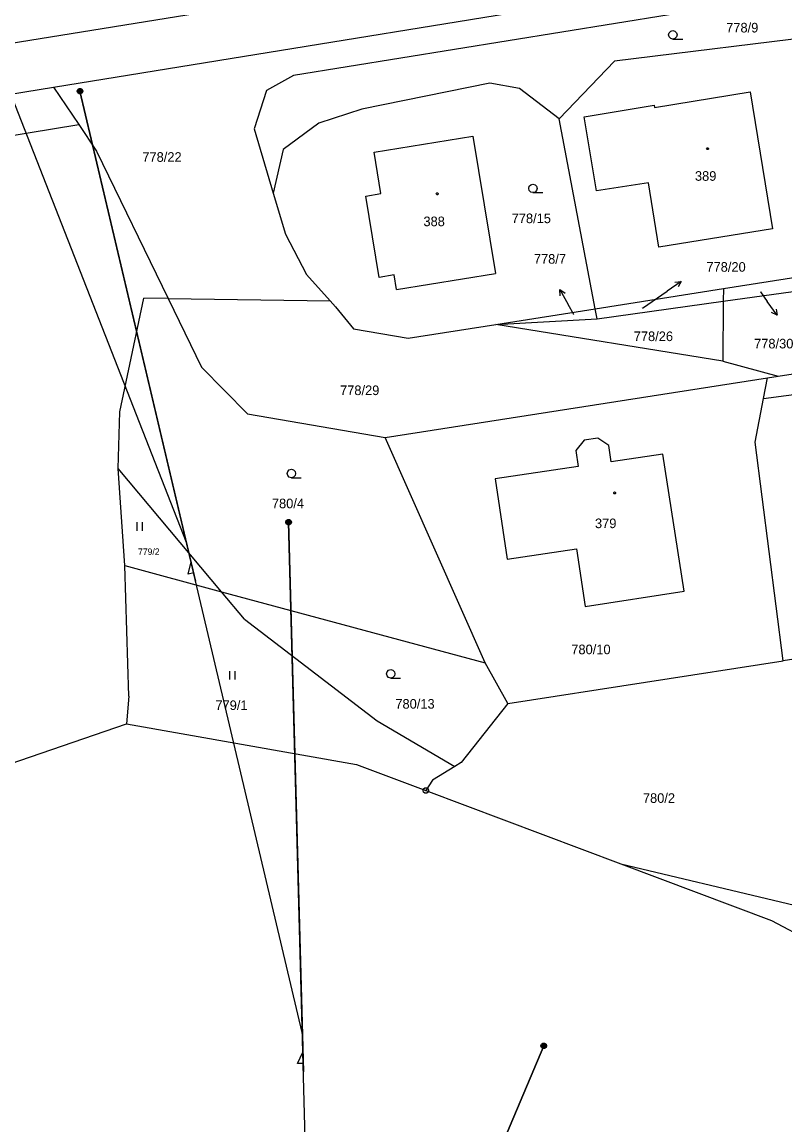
# Model space of a CAD drawing. Extents: x -747792 to -745414, y -1093712 to -1091463.
# Drawn here: x -746030.8 to -745963.3, y -1091690.6 to -1091593 of the extents above; entities that cross this region are included whole.
import ezdxf

# ---------------------------------------------------------------- set-up
doc = ezdxf.new("R2010")
doc.units = 0
for name, color, linetype in [('Budovy', 7, 'Continuous'), ('Doplňkové značky', 7, 'Continuous'), ('Doplňující texty', 7, 'Continuous'), ('Koleje_dopravní prvky', 7, 'Continuous'), ('Kultury', 7, 'Continuous'), ('Ploty_opěrné zdi', 7, 'Continuous'), ('Stromy_porost', 7, 'Continuous'), ('Značky IS', 7, 'Continuous')]:
    doc.layers.add(name, color=color, linetype=linetype)

msp = doc.modelspace()

# ---------------------------------------------------------------- linework, layer by layer
at = {"layer": 'Budovy'}
for points in [[(-745973.24, -1091594.46), (-745973.43, -1091594.41), (-745973.565, -1091594.27), (-745973.615, -1091594.085), (-745973.565, -1091593.9), (-745973.43, -1091593.76), (-745973.24, -1091593.71), (-745973.05, -1091593.76), (-745972.915, -1091593.9), (-745972.865, -1091594.085), (-745972.915, -1091594.27), (-745973.05, -1091594.41), (-745973.24, -1091594.46), (-745972.365, -1091594.46)], [(-745985.62, -1091608.06), (-745985.81, -1091608.01), (-745985.945, -1091607.87), (-745985.995, -1091607.685), (-745985.945, -1091607.5), (-745985.81, -1091607.36), (-745985.62, -1091607.31), (-745985.43, -1091607.36), (-745985.295, -1091607.5), (-745985.245, -1091607.685), (-745985.295, -1091607.87), (-745985.43, -1091608.01), (-745985.62, -1091608.06), (-745984.745, -1091608.06)], [(-746007, -1091633.3), (-746007.19, -1091633.25), (-746007.325, -1091633.11), (-746007.375, -1091632.925), (-746007.325, -1091632.74), (-746007.19, -1091632.6), (-746007, -1091632.55), (-746006.81, -1091632.6), (-746006.675, -1091632.74), (-746006.625, -1091632.925), (-746006.675, -1091633.11), (-746006.81, -1091633.25), (-746007, -1091633.3), (-746006.125, -1091633.3)], [(-746020.67, -1091637.24), (-746020.67, -1091637.99)], [(-746020.17, -1091637.99), (-746020.17, -1091637.24)], [(-746012.47, -1091650.41), (-746012.47, -1091651.16)], [(-746011.97, -1091651.16), (-746011.97, -1091650.41)], [(-745998.21, -1091651.03), (-745998.4, -1091650.98), (-745998.535, -1091650.84), (-745998.585, -1091650.655), (-745998.535, -1091650.47), (-745998.4, -1091650.33), (-745998.21, -1091650.28), (-745998.02, -1091650.33), (-745997.885, -1091650.47), (-745997.835, -1091650.655), (-745997.885, -1091650.84), (-745998.02, -1091650.98), (-745998.21, -1091651.03), (-745997.335, -1091651.03)]]:
    msp.add_lwpolyline(points, dxfattribs=at)
at = {"layer": 'Doplňkové značky'}
for points in [[(-745983.244, -1091616.648), (-745982.5, -1091617.95)], [(-745983.213, -1091617.206), (-745983.244, -1091616.648), (-745982.779, -1091616.958)], [(-745972.507, -1091615.916), (-745973.74, -1091616.77)], [(-745973.06, -1091615.995), (-745972.507, -1091615.916), (-745972.776, -1091616.406)], [(-745975.92, -1091618.28), (-745973.74, -1091616.77)], [(-745965.49, -1091616.85), (-745964.88, -1091617.7)], [(-745964.006, -1091618.919), (-745964.88, -1091617.7)], [(-745981.99, -1091618.85), (-745982.5, -1091617.95)], [(-745964.094, -1091618.367), (-745964.006, -1091618.919), (-745964.5, -1091618.658)]]:
    msp.add_lwpolyline(points, dxfattribs=at)
at = {"layer": 'Doplňující texty'}
msp.add_lwpolyline([(-745995.025, -1091660.75), (-745994.9, -1091660.845), (-745994.85, -1091660.99), (-745994.9, -1091661.135), (-745995.025, -1091661.23), (-745995.175, -1091661.23), (-745995.3, -1091661.135), (-745995.35, -1091660.99), (-745995.3, -1091660.845), (-745995.175, -1091660.75)], close=True, dxfattribs=at)
msp.add_lwpolyline([(-745995.125, -1091660.99), (-745995.075, -1091660.99)], dxfattribs=at)
at = {"layer": 'Kultury'}
msp.add_lwpolyline([(-746047.89, -1091597.41), (-745968.74, -1091584.63)], dxfattribs=at)
at = {"layer": 'Ploty_opěrné zdi'}
for points in [[(-745970.17, -1091604.085), (-745970.12, -1091604.095), (-745970.095, -1091604.14), (-745970.085, -1091604.17), (-745970.095, -1091604.215), (-745970.135, -1091604.25), (-745970.17, -1091604.255), (-745970.215, -1091604.24), (-745970.245, -1091604.21), (-745970.255, -1091604.17), (-745970.245, -1091604.125), (-745970.205, -1091604.09)], [(-745994.09, -1091608.075), (-745994.04, -1091608.085), (-745994.015, -1091608.13), (-745994.005, -1091608.16), (-745994.015, -1091608.205), (-745994.055, -1091608.24), (-745994.09, -1091608.245), (-745994.135, -1091608.23), (-745994.165, -1091608.2), (-745994.175, -1091608.16), (-745994.165, -1091608.115), (-745994.125, -1091608.08)], [(-745978.39, -1091634.555), (-745978.34, -1091634.565), (-745978.315, -1091634.61), (-745978.305, -1091634.64), (-745978.315, -1091634.685), (-745978.355, -1091634.72), (-745978.39, -1091634.725), (-745978.435, -1091634.71), (-745978.465, -1091634.68), (-745978.475, -1091634.64), (-745978.465, -1091634.595), (-745978.425, -1091634.56)]]:
    msp.add_lwpolyline(points, close=True, dxfattribs=at)
at = {"layer": 'Stromy_porost'}
for points in [[(-746028.05, -1091598.72), (-745968.8, -1091589.06)], [(-745968.83, -1091591.55), (-746006.8, -1091597.68)], [(-745959.19, -1091594.06), (-745978.41, -1091596.41)], [(-745978.41, -1091596.41), (-745983.31, -1091601.54)], [(-746006.8, -1091597.68), (-746009.21, -1091599.02)], [(-746046.56, -1091601.74), (-746028.05, -1091598.72)], [(-746028.05, -1091598.72), (-746025.82, -1091602.04)], [(-746009.21, -1091599.02), (-746010.28, -1091602.42)], [(-745989.44, -1091598.37), (-746000.77, -1091600.68)], [(-745986.8, -1091598.84), (-745989.44, -1091598.37)], [(-745983.31, -1091601.54), (-745986.8, -1091598.84)], [(-745974.86, -1091600.51), (-745966.39, -1091599.13)], [(-745966.39, -1091599.13), (-745964.41, -1091611.26)], [(-746000.77, -1091600.68), (-746004.58, -1091601.91)], [(-745981.09, -1091601.36), (-745974.88, -1091600.33)], [(-745974.88, -1091600.33), (-745974.86, -1091600.51)], [(-746041.61, -1091604.62), (-746025.82, -1091602.04)], [(-746025.82, -1091602.04), (-746024.25, -1091604.39)], [(-746004.58, -1091601.91), (-746007.72, -1091604.24)], [(-745980.12, -1091618.34), (-745983.31, -1091601.54)], [(-745980.01, -1091607.91), (-745981.09, -1091601.36)], [(-746010.28, -1091602.42), (-746008.61, -1091608.11)], [(-745999.67, -1091604.47), (-745990.93, -1091603.06)], [(-745990.93, -1091603.06), (-745988.93, -1091615.23)], [(-746024.25, -1091604.39), (-746017.9, -1091617.43)], [(-746007.72, -1091604.24), (-746008.61, -1091608.11)], [(-745999.08, -1091608.14), (-745999.67, -1091604.47)], [(-745975.4, -1091607.19), (-745980.01, -1091607.91)], [(-745974.48, -1091612.9), (-745975.4, -1091607.19)], [(-746008.61, -1091608.11), (-746007.53, -1091611.75)], [(-746000.41, -1091608.36), (-745999.08, -1091608.14)], [(-745999.24, -1091615.56), (-746000.41, -1091608.36)], [(-746007.53, -1091611.75), (-746005.66, -1091615.32)], [(-745964.41, -1091611.26), (-745974.48, -1091612.9)], [(-745968.77, -1091616.55), (-745955.77, -1091614.51)], [(-746005.66, -1091615.32), (-746003.57, -1091617.65)], [(-745997.91, -1091615.35), (-745999.24, -1091615.56)], [(-745997.7, -1091616.63), (-745997.91, -1091615.35)], [(-745997.7, -1091616.63), (-745988.93, -1091615.23)], [(-745980.12, -1091618.34), (-745968.77, -1091616.55)], [(-745968.78, -1091617.68), (-745955.54, -1091615.85)], [(-745968.77, -1091616.55), (-745968.78, -1091617.68)], [(-746022.18, -1091627.45), (-746020.05, -1091617.4)], [(-746017.9, -1091617.43), (-746020.05, -1091617.4)], [(-746017.9, -1091617.43), (-746003.57, -1091617.65)], [(-746017.9, -1091617.43), (-746014.94, -1091623.51)], [(-746003.57, -1091617.65), (-746003.09, -1091618.18)], [(-745979.95, -1091619.23), (-745968.78, -1091617.68)], [(-745968.78, -1091617.68), (-745968.83, -1091622.99)], [(-746003.09, -1091618.18), (-746001.49, -1091620.11)], [(-745988.92, -1091619.73), (-745980.12, -1091618.34)], [(-745979.95, -1091619.23), (-745980.12, -1091618.34)], [(-745988.92, -1091619.73), (-745979.95, -1091619.23)], [(-746001.49, -1091620.11), (-745996.67, -1091620.95)], [(-745996.67, -1091620.95), (-745988.92, -1091619.73)], [(-745968.83, -1091622.99), (-745988.92, -1091619.73)], [(-745963.91, -1091624.31), (-745946.44, -1091621.58)], [(-746014.94, -1091623.51), (-746010.87, -1091627.63)], [(-745968.83, -1091622.99), (-745963.91, -1091624.31)], [(-745965.23, -1091626.27), (-745941.81, -1091623.17)], [(-745998.7, -1091629.75), (-745964.87, -1091624.46)], [(-745965.23, -1091626.27), (-745964.87, -1091624.46)], [(-745964.87, -1091624.46), (-745963.91, -1091624.31)], [(-745965.97, -1091630.16), (-745965.23, -1091626.27)], [(-746022.34, -1091632.47), (-746022.18, -1091627.45)], [(-746010.87, -1091627.63), (-745998.7, -1091629.75)], [(-745989.84, -1091649.69), (-745998.7, -1091629.75)], [(-745981.09, -1091629.96), (-745981.83, -1091630.88)], [(-745979.89, -1091629.78), (-745981.09, -1091629.96)], [(-745978.92, -1091630.43), (-745979.89, -1091629.78)], [(-745978.71, -1091631.88), (-745978.92, -1091630.43)], [(-745963.48, -1091649.5), (-745965.97, -1091630.16)], [(-745981.83, -1091630.88), (-745981.63, -1091632.31)], [(-745974.14, -1091631.2), (-745978.71, -1091631.88)], [(-745972.25, -1091643.33), (-745974.14, -1091631.2)], [(-745981.63, -1091632.31), (-745988.95, -1091633.4)], [(-746021.73, -1091641.08), (-746022.34, -1091632.47)], [(-746013.19, -1091643.39), (-746022.34, -1091632.47)], [(-745988.95, -1091633.4), (-745987.89, -1091640.51)], [(-745987.89, -1091640.51), (-745981.76, -1091639.58)], [(-745981.76, -1091639.58), (-745980.99, -1091644.7)], [(-746021.37, -1091652.64), (-746021.73, -1091641.08)], [(-746021.73, -1091641.08), (-746013.19, -1091643.39)], [(-746013.19, -1091643.39), (-745989.84, -1091649.69)], [(-746011.15, -1091645.82), (-746013.19, -1091643.39)], [(-745980.99, -1091644.7), (-745972.25, -1091643.33)], [(-746011.15, -1091645.82), (-745999.4, -1091654.83)], [(-745945.61, -1091646.72), (-745963.48, -1091649.5)], [(-745987.84, -1091653.29), (-745989.84, -1091649.69)], [(-745987.84, -1091653.29), (-745963.48, -1091649.5)], [(-746021.37, -1091652.64), (-746021.58, -1091655.08)], [(-745987.84, -1091653.29), (-745991.96, -1091658.52), (-745992.53, -1091658.86)], [(-745999.4, -1091654.83), (-745992.53, -1091658.86)], [(-746172.9, -1091707.09), (-746021.58, -1091655.08)], [(-746021.58, -1091655.08), (-746001.24, -1091658.68)], [(-746001.24, -1091658.68), (-745995.1, -1091660.99)], [(-745992.53, -1091658.86), (-745994.51, -1091660.06), (-745995.1, -1091660.99)], [(-745995.1, -1091660.99), (-745977.84, -1091667.47)], [(-745977.84, -1091667.47), (-745964.51, -1091672.48)], [(-745977.84, -1091667.47), (-745949.59, -1091674.19)], [(-745964.51, -1091672.48), (-745950.71, -1091679.81)]]:
    msp.add_lwpolyline(points, dxfattribs=at)
at = {"layer": 'Značky IS'}
for points in [[(-746016.274, -1091639.038), (-746060.98, -1091524.93), (-746037.989, -1091583.613)], [(-746025.785, -1091598.84), (-746025.63, -1091598.84), (-746025.505, -1091598.93), (-746025.455, -1091599.075), (-746025.505, -1091599.22), (-746025.63, -1091599.31), (-746025.785, -1091599.31), (-746025.91, -1091599.22), (-746025.96, -1091599.075), (-746025.91, -1091598.93), (-746025.785, -1091598.84), (-746025.77, -1091598.86), (-746025.65, -1091598.86), (-746025.57, -1091598.9), (-746025.85, -1091598.9), (-746025.89, -1091598.94), (-746025.53, -1091598.94), (-746025.53, -1091598.98), (-746025.89, -1091598.98), (-746025.91, -1091599.02), (-746025.51, -1091599.02), (-746025.49, -1091599.06), (-746025.93, -1091599.06), (-746025.93, -1091599.1), (-746025.49, -1091599.1), (-746025.505, -1091599.14), (-746025.91, -1091599.14), (-746025.905, -1091599.18), (-746025.5, -1091599.18), (-746025.525, -1091599.22), (-746025.885, -1091599.22), (-746025.845, -1091599.26), (-746025.565, -1091599.26), (-746025.62, -1091599.3), (-746025.79, -1091599.3)], [(-746006.034, -1091682.403), (-746025.71, -1091599.08), (-746015.47, -1091642.444)], [(-746007.325, -1091637), (-746007.17, -1091637), (-746007.045, -1091637.09), (-746006.995, -1091637.235), (-746007.045, -1091637.38), (-746007.17, -1091637.47), (-746007.325, -1091637.47), (-746007.45, -1091637.38), (-746007.5, -1091637.235), (-746007.45, -1091637.09), (-746007.325, -1091637), (-746007.31, -1091637.02), (-746007.19, -1091637.02), (-746007.11, -1091637.06), (-746007.39, -1091637.06), (-746007.43, -1091637.1), (-746007.07, -1091637.1), (-746007.07, -1091637.14), (-746007.43, -1091637.14), (-746007.45, -1091637.18), (-746007.05, -1091637.18), (-746007.03, -1091637.22), (-746007.47, -1091637.22), (-746007.47, -1091637.26), (-746007.03, -1091637.26), (-746007.045, -1091637.3), (-746007.45, -1091637.3), (-746007.445, -1091637.34), (-746007.04, -1091637.34), (-746007.065, -1091637.38), (-746007.425, -1091637.38), (-746007.385, -1091637.42), (-746007.105, -1091637.42), (-746007.16, -1091637.46), (-746007.33, -1091637.46)], [(-746004.724, -1091731.064), (-746007.25, -1091637.24), (-746005.94, -1091685.901)], [(-746015.527, -1091642.201), (-746015.642, -1091641.715), (-746016.129, -1091641.829), (-746015.872, -1091640.741), (-746016.217, -1091639.281)], [(-746005.947, -1091685.651), (-746005.96, -1091685.152), (-746006.46, -1091685.165), (-746005.987, -1091684.152), (-746006.028, -1091682.652)], [(-746026.14, -1091781.772), (-745984.67, -1091683.58), (-746006.086, -1091734.288)], [(-745984.745, -1091683.34), (-745984.59, -1091683.34), (-745984.465, -1091683.43), (-745984.415, -1091683.575), (-745984.465, -1091683.72), (-745984.59, -1091683.81), (-745984.745, -1091683.81), (-745984.87, -1091683.72), (-745984.92, -1091683.575), (-745984.87, -1091683.43), (-745984.745, -1091683.34), (-745984.73, -1091683.36), (-745984.61, -1091683.36), (-745984.53, -1091683.4), (-745984.81, -1091683.4), (-745984.85, -1091683.44), (-745984.49, -1091683.44), (-745984.49, -1091683.48), (-745984.85, -1091683.48), (-745984.87, -1091683.52), (-745984.47, -1091683.52), (-745984.45, -1091683.56), (-745984.89, -1091683.56), (-745984.89, -1091683.6), (-745984.45, -1091683.6), (-745984.465, -1091683.64), (-745984.87, -1091683.64), (-745984.865, -1091683.68), (-745984.46, -1091683.68), (-745984.485, -1091683.72), (-745984.845, -1091683.72), (-745984.805, -1091683.76), (-745984.525, -1091683.76), (-745984.58, -1091683.8), (-745984.75, -1091683.8)]]:
    msp.add_lwpolyline(points, dxfattribs=at)

# ---------------------------------------------------------------- texts
at = {"layer": 'Doplňkové značky'}
for s, p in [('778/7', (-745985.539, -1091614.35)), ('778/20', (-745970.27, -1091615.06)), ('778/30', (-745966.05, -1091621.85))]:
    msp.add_text(s, height=0.85, dxfattribs=at).set_placement(p)
at = {"layer": 'Koleje_dopravní prvky'}
for s, height, p in [('778/9', 0.85, (-745968.52, -1091593.88)), ('778/22', 0.85, (-746020.188, -1091605.33)), ('389', 0.85, (-745971.284, -1091607.01)), ('778/15', 0.85, (-745987.504, -1091610.76)), ('388', 0.85, (-745995.314, -1091611.03)), ('778/26', 0.85, (-745976.701, -1091621.2)), ('778/29', 0.85, (-746002.691, -1091625.98)), ('780/4', 0.85, (-746008.723, -1091636)), ('379', 0.85, (-745980.131, -1091637.76)), ('779/2', 0.57, (-746020.569, -1091640.13)), ('780/10', 0.85, (-745982.227, -1091648.92)), ('780/13', 0.85, (-745997.797, -1091653.74)), ('779/1', 0.85, (-746013.722, -1091653.86)), ('780/2', 0.85, (-745975.89, -1091662.08))]:
    msp.add_text(s, height=height, dxfattribs=at).set_placement(p)
for s, rotation, p in [('778/30', 10.08406, (-745965.611, -1091616.872)), ('778/20', 9.5111, (-745976.041, -1091618.3)), ('778/7', 6.99009, (-745982.087, -1091618.862))]:
    msp.add_text(s, height=0.05, rotation=rotation, dxfattribs=at).set_placement(p)

doc.saveas('drawing.dxf')
